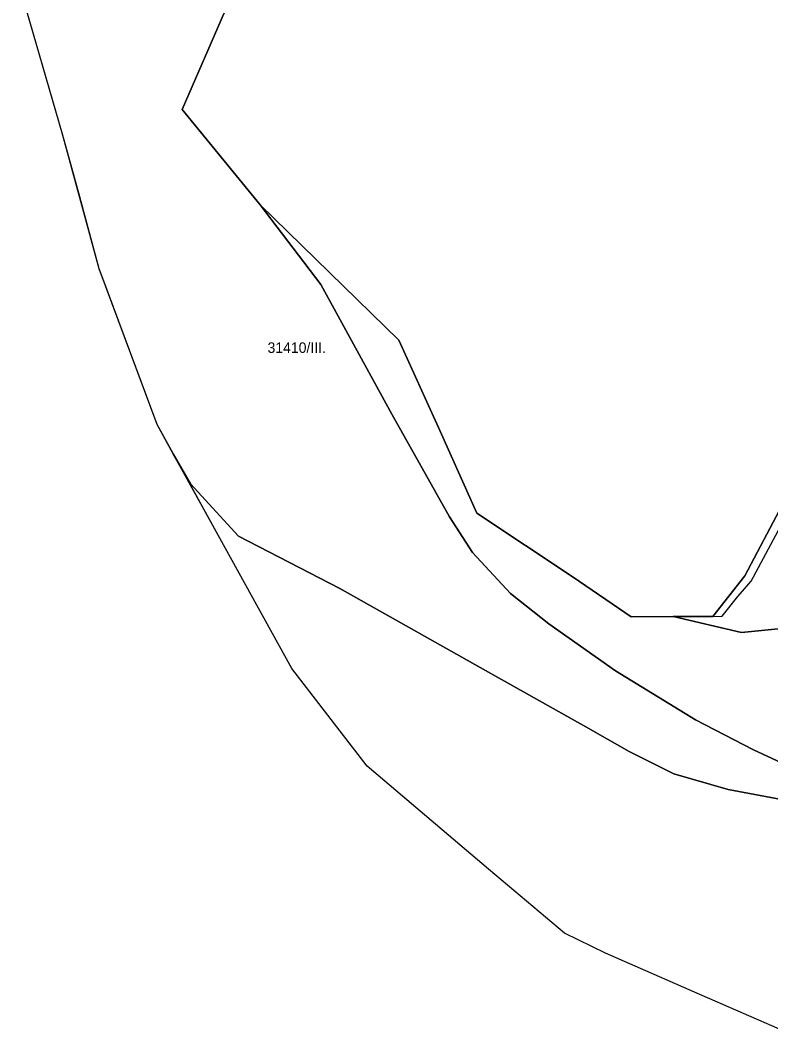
# Model space of a CAD drawing. Extents: x -532083 to -529270, y -1180561 to -1176456.
# Drawn here: x -531002.4 to -530643.9, y -1180171.1 to -1179686.6 of the extents above; entities that cross this region are included whole.
import ezdxf

# ---------------------------------------------------------------- set-up
doc = ezdxf.new("R2010")
doc.units = 0
for name, color, linetype in [('95560013', 7, 'Continuous'), ('95610013', 7, 'Continuous'), ('95620013', 7, 'Continuous'), ('95660013', 7, 'Continuous')]:
    doc.layers.add(name, color=color, linetype=linetype)

msp = doc.modelspace()

# ---------------------------------------------------------------- linework, layer by layer
at = {"layer": '95560013'}
for points in [[(-530624.0833, -1179110.25145), (-530692.4043, -1179279.29745), (-530711.6183, -1179327.08245), (-530752.8893, -1179428.87345), (-530780.3383, -1179501.33545), (-530792.0203, -1179529.85045), (-530840.3343, -1179531.93145), (-530866.4173, -1179584.85745), (-530883.0153, -1179626.18745), (-530904.8823, -1179682.75545), (-530925.0953, -1179729.23645), (-530887.7793, -1179774.78045), (-530858.8613, -1179812.72545), (-530824.8703, -1179874.67145), (-530797.3943, -1179923.83045), (-530786.3453, -1179940.81745), (-530768.2873, -1179960.35245), (-530749.8763, -1179974.91445), (-530718.0113, -1179997.29145), (-530679.7723, -1180020.73345), (-530652.1383, -1180035.12045), (-530616.5163, -1180051.56345)], [(-530633.4093, -1180171.13445), (-530680.2893, -1180150.82445), (-530722.8103, -1180132.24845), (-530742.3563, -1180122.61745), (-530778.7043, -1180092.00145), (-530836.6553, -1180042.81145), (-530872.7033, -1179996.21545), (-530907.8543, -1179932.49545), (-530937.0383, -1179879.71445), (-530964.7323, -1179805.22545), (-530982.2063, -1179740.95245), (-531002.4393, -1179671.14445)]]:
    msp.add_lwpolyline(points, dxfattribs=at)
at = {"layer": '95610013'}
msp.add_lwpolyline([(-530679.7723, -1180020.73345), (-530718.0113, -1179997.29145), (-530749.8763, -1179974.91445), (-530768.2873, -1179960.35245), (-530786.3453, -1179940.81745), (-530797.3943, -1179923.83045), (-530824.8703, -1179874.67145), (-530858.8613, -1179812.72545), (-530887.7793, -1179774.78045), (-530821.6083, -1179839.30245), (-530802.5813, -1179881.01145), (-530784.2593, -1179922.01445), (-530738.3333, -1179952.54645), (-530710.5303, -1179971.53645), (-530671.4873, -1179971.33845), (-530667.1493, -1179971.14045), (-530659.6563, -1179961.84345), (-530653.1493, -1179954.52445), (-530635.5993, -1179921.49045), (-530627.3183, -1179920.69945), (-530624.6023, -1179962.11545), (-530622.1983, -1179994.12345), (-530616.5163, -1180051.56345), (-530652.1383, -1180035.12045)], close=True, dxfattribs=at)
at = {"layer": '95620013'}
msp.add_lwpolyline([(-530638.1853, -1179917.86845), (-530656.2083, -1179951.88945), (-530671.4873, -1179971.33845), (-530710.5303, -1179971.53645), (-530738.3333, -1179952.54645), (-530784.2593, -1179922.01445), (-530802.5813, -1179881.01145), (-530821.6083, -1179839.30245), (-530887.7793, -1179774.78045), (-530925.0953, -1179729.23645), (-530904.8823, -1179682.75545), (-530883.0153, -1179626.18745), (-530866.4173, -1179584.85745), (-530840.3343, -1179531.93145), (-530792.0203, -1179529.85045), (-530780.3383, -1179501.33545), (-530752.8893, -1179428.87345), (-530711.6183, -1179327.08245), (-530692.4043, -1179279.29745), (-530624.0833, -1179110.25145)], dxfattribs=at)
at = {"layer": '95660013'}
for points in [[(-530638.1853, -1179917.86845), (-530656.2083, -1179951.88945), (-530671.4873, -1179971.33845), (-530690.4433, -1179971.43445), (-530710.5303, -1179971.53645), (-530738.3333, -1179952.54645), (-530784.2593, -1179922.01445), (-530802.5813, -1179881.01145), (-530821.6083, -1179839.30245), (-530887.7793, -1179774.78045), (-530925.0953, -1179729.23645), (-530904.8823, -1179682.75545), (-530901.7523, -1179674.65945), (-530883.0153, -1179626.18745), (-530866.4173, -1179584.85745), (-530840.3343, -1179531.93145), (-530792.0203, -1179529.85045), (-530780.3383, -1179501.33545), (-530752.8893, -1179428.87345), (-530711.6183, -1179327.08245), (-530692.4043, -1179279.29745), (-530624.0833, -1179110.25145)], [(-530638.7893, -1180058.83745), (-530664.1823, -1180054.08145), (-530690.1013, -1180046.50345), (-530711.4993, -1180035.79945), (-530732.2553, -1180024.10845), (-530775.0593, -1180000.00045), (-530849.8123, -1179958.00045), (-530898.1873, -1179933.00045), (-530921.1253, -1179908.00045), (-530929.3223, -1179893.66845), (-530937.0383, -1179879.71445), (-530962.9873, -1179809.91745), (-530964.7323, -1179805.22545), (-530974.0423, -1179770.97845), (-530974.0553, -1179770.93545), (-530977.8223, -1179757.07745), (-530982.2063, -1179740.95245), (-531002.4393, -1179671.14445)], [(-530904.8823, -1179682.75545), (-530925.0953, -1179729.23645), (-530887.7793, -1179774.78045), (-530821.6083, -1179839.30245), (-530802.5813, -1179881.01145), (-530784.2593, -1179922.01445), (-530738.3333, -1179952.54645), (-530710.5303, -1179971.53645), (-530690.4433, -1179971.43445), (-530657.8753, -1179979.00045), (-530608.6873, -1179974.00045)], [(-530633.4093, -1180171.13445), (-530680.2893, -1180150.82445), (-530722.8103, -1180132.24845), (-530742.3563, -1180122.61745), (-530778.7043, -1180092.00145), (-530836.6553, -1180042.81145), (-530872.7033, -1179996.21545), (-530907.8543, -1179932.49545), (-530929.3223, -1179893.66845), (-530921.1253, -1179908.00045), (-530898.1873, -1179933.00045), (-530849.8123, -1179958.00045), (-530775.0593, -1180000.00045), (-530732.2553, -1180024.10845), (-530711.4993, -1180035.79945), (-530690.1013, -1180046.50345), (-530664.1823, -1180054.08145), (-530638.7893, -1180058.83745)], [(-530608.6873, -1179974.00045), (-530657.8753, -1179979.00045), (-530690.4433, -1179971.43445), (-530671.4873, -1179971.33845), (-530656.2083, -1179951.88945), (-530638.1853, -1179917.86845)]]:
    msp.add_lwpolyline(points, dxfattribs=at)

# ---------------------------------------------------------------- texts
msp.add_text('31410/III.', height=5, rotation=0, dxfattribs=at).set_placement((-530884.29547, -1179845.43795))

doc.saveas('drawing.dxf')
